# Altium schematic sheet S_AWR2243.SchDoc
size 431 x 279 mm; SheetNumber: 3; SheetTotal: 4; PageSetup: Record=PageOptions¦CenterHorizontal=True¦CenterVertical=True¦PrintScale=1.01¦XCorrection=1.00¦YCorrection=1.00¦PrintKind=1¦BorderSize=5000000¦LeftOffset=0¦BottomOffset=0¦Orientation=2¦PaperLength=1000¦PaperWidth=1000¦Scale=100¦PaperSource=7¦PrintQuality=600¦MediaType=1¦DitherType=10¦PaperKind=A3¦PrintScaleMode=1; SPICEModelCacheFJOGIKSH: <root> / <DocumentId>FJOGIKSH</DocumentId> / </root>; ENG_APP_DATE: --/--/--; DSN_APP_DATE: --/--/--; CHK_APP_DATE: --/--/--
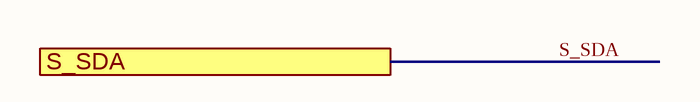
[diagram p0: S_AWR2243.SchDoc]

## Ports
S_SDA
